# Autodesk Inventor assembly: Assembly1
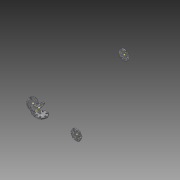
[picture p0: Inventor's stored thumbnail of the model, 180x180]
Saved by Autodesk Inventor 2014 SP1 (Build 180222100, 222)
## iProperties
Created: 2015-02
Part Number: Assembly1
Document SubType Name: Assembly
Designer: Mohamed
Author: Mohamed
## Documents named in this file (2)
- C:\Users\Mohamed\Documents\inventor\ConstructionSet\Assembly1.iam
- C:\Users\Mohamed\Documents\inventor\ConstructionSet\piece.ipt
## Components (6 placed, 1 different names)
1. piece:1 — Mate:4, Mate:5, Mate:6
2. piece:2 — Mate:1, Mate:2, Mate:3, Mate:4, Mate:5, Mate:6, Mate:7, Mate:8, Mate:9
3. piece:3 — Mate:7, Mate:8, Mate:9
4. piece:4
5. piece:5 — Mate:1, Mate:2, Mate:3
6. piece:6
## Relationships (9: Mate 9)
- Mate:1: piece:2 ↔ piece:5
- Mate:2: piece:2 ↔ piece:5
- Mate:3: piece:2 ↔ piece:5
- Mate:4: piece:1 ↔ piece:2
- Mate:5: piece:1 ↔ piece:2
- Mate:6: piece:1 ↔ piece:2
- Mate:7: piece:2 ↔ piece:3
- Mate:8: piece:2 ↔ piece:3
- Mate:9: piece:2 ↔ piece:3
